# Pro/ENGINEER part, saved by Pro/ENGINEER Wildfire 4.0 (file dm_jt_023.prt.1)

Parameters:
  METRIC = "NO"

Other parameters: PITCH, DRILL_DIAMETER, THREAD_DIAMETER, THREADS_PER_INCH, CBORE_DIAMETER, CBORE_DEPTH, DRILL_POINT_ANGLE, DRILL_DEPTH, THREAD_DEPTH, THREAD_LENGTH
